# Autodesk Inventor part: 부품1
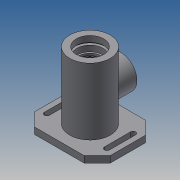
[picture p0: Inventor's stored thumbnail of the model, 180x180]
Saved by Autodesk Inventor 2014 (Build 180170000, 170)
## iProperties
Created: 2017-10
Part Number: 부품1
Material: 일반
Document SubType Name: Modeling
Designer: NET
Density: 1 g/cm^3
Appearance: 기본값
Author: NET
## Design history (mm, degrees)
sketch "스케치1"
  geometry: L1 (-58, 47)-(58, 47); L2 (58, 47)-(58, -47); L3 (58, -47)-(-58, -47); L4 (-58, -47)-(-58, 47); C1 r 31 at (0, 0); C2 r 35 at (0, 0); 3 further points
  constraints: 8 end point, 2 centre point, 2 coincident, 2 midpoint, 2 parallel, 1 horizontal, 1 horizontal alignment, 1 perpendicular, 1 vertical alignment
  dimensions: "d0" = 62 diameter of C1; "d1" = 116 distance of L1.start L1.end; "d2" = 94 distance of L1.end L2.end; "d3" = 70 diameter of C2
extrude "돌출1" new body sketch "스케치1" distance "d4" = 10; taper "d5" = 0 deg
extrude "돌출2" join sketch "스케치1" distance "d6" = 13; taper "d7" = 0 deg
extrude "돌출3" join sketch "스케치1" distance "d8" = 102; taper "d9" = 0 deg
chamfer "모따기1" distance "d10" = 20; stored, may be unused: second distance "d11" = 2, angle "d12" = 45 deg
node "작업 평면1"
sketch "스케치2"
  geometry: L1 (38, 0)-(-38, 0) reference; L2 (31, 102)-(-31, 102) reference; C1 r 25 at (0, 46); 2 further points
  constraints: 1 centre point, 1 midpoint, 1 vertical alignment
  dimensions: "d13" = 50 diameter of C1; "d14" = 56 distance from line of C1.centre L2
extrude "돌출4" join sketch "스케치2" stored distance "d15" = 32; taper "d16" = 0 deg
sketch "스케치3"
  geometry: L1 (-38, -47)-(38, -47) reference; L2 (-46, 20)-(-46, -20); L3 (-50, 20)-(-50, -20); L4 (-42, -20)-(-42, 20); L5 (46, 20)-(46, -20); L6 (42, 20)-(42, -20); L7 (50, -20)-(50, 20); C1 r 35 at (0, 0) reference; A1 r 4 centre (-46, 20) between (-42, 20) and (-50, 20); A2 r 4 centre (-46, -20) between (-50, -20) and (-42, -20); A3 r 4 centre (46, 20) between (50, 20) and (42, 20); A4 r 4 centre (46, -20) between (42, -20) and (50, -20); 2 further points
  constraints: 16 end point, 8 point on circle, 8 tangent, 4 centre point, 4 parallel, 2 horizontal alignment, 2 midpoint, 1 perpendicular
  dimensions: "d17" = 46 distance of point (-46, 0) C1.centre; "d18" = 92 distance of point (46, 0) point (-46, 0); "d19" = 40 distance of L5.end L5.start; "d20" = 4 radius of A3; "d21" = 4 radius of A1
extrude "돌출5" cut sketch "스케치3" distance "d22" = 32; taper "d23" = 0 deg
extrude "돌출6" join sketch "스케치1" distance "d24" = 13; taper "d25" = 0 deg
sketch "스케치4"
  geometry: L1 (31, 102)-(-31, 102) reference; L2 (31, 0)-(31, 102) reference; L3 (-31, 0)-(31, 0) reference; L4 (21, 93)-(24, 93); L5 (24, 93)-(24, 90); L6 (24, 90)-(20, 90); L7 (20, 90)-(20, 81); L8 (20, 81)-(17.5, 81); L9 (17.5, 81)-(17.5, 77.75); L10 (17.5, 77.75)-(18.5, 77.75); L11 (18.5, 77.75)-(18.5, 76); L12 (18.5, 76)-(17.5, 76); L13 (17.5, 76)-(17.5, 65); L14 (17.5, 65)-(23, 65); L15 (26, 62)-(26, 30); L16 (23, 27)-(17.5, 27); L17 (17.5, 27)-(17.5, 16.3); L18 (17.2, 16)-(16.5, 16); L19 (16.5, 16)-(16.5, 14); L20 (13.5, 11)-(10, 11); L21 (10, 11)-(10, 8.3); L22 (10, 8.3)-(12.2, 8.3); L23 (12.5, 8)-(12.5, 1.7); L24 (12.904, 1)-(14.022, 1); L25 (0, 102)-(0, 0); L26 (21, 93)-(21, 102); L27 (16.779, -0.818)-(22, -13); L28 (-35, -13)-(35, -13) reference; L29 (22, -13)-(0, -13); L30 (0, 0)-(0, -13); L31 (12.5, 1.7)-(12.904, 1); A1 r 3 centre (23, 30) between (23, 27) and (26, 30); A2 r 3 centre (23, 62) between (26, 62) and (23, 65); A3 r 3 centre (13.5, 14) between (13.5, 11) and (16.5, 14); A4 r 3 centre (14.022, -2) between (16.779, -0.818) and (14.022, 1); A5 r 0.3 centre (17.2, 16.3) between (17.2, 16) and (17.5, 16.3); A6 r 0.3 centre (12.2, 8) between (12.5, 8) and (12.2, 8.3); 7 further points
  constraints: 54 end point, 16 point on line, 14 perpendicular, 12 point on circle, 12 tangent, 10 parallel, 6 centre point, 4 equal radius, 2 collinear, 2 midpoint
  dimensions: "d26" = 42 diameter of L26 L25; "d27" = 40 diameter of L7 L25; "d28" = 48 diameter of L5 L25; "d29" = 35 diameter of L9 L25; "d30" = 37 diameter of L11 L25; "d31" = 52 diameter of L15 L25; "d33" = 33 diameter of L19 L25; "d34" = 20 diameter of L21 L25; "d35" = 25 diameter of L23 L25; "d36" = 32 diameter of point (16, 1) L25; "d38" = 12 distance from line of L26.end L6; "d39" = 3 distance of L4.end L5.end; "d40" = 21 distance from line of L1 L7.end; "d42" = 26 distance from line of L1 L11.end; "d43" = 1.75 distance of L10.end L11.end; "d44" = 38 distance of point (26, 65) point (26, 27); "d45" = 60 vertical distance of L12.end L18.end; "d46" = 14 distance from line of L24 L27.end; "d48" = 2.7 distance between parallel lines of L20 L22; "d49" = 7.3 distance between parallel lines of L22 L24; "d50" = 11 distance from line of L12.end L14; "d51" = 44 diameter of L27.end L25; "d53" = 3 radius of A1; "d54" = 0.3 radius of A5; "d55" = 0.7 distance of L23.end point (12.5, 1); "d56" = 30 deg angle of L23 L31
revolve "회전1" sketch "스케치4" stored, may be unused: angle "d52" = 90 deg
sketch "스케치5"
  geometry: C1 r 25 at (0, 0) reference; C2 r 16 at (0, 0); 1 further point
  constraints: 1 centre point, 1 coincident
  dimensions: "d57" = 32 diameter of C2
extrude "돌출7" cut sketch "스케치5" distance "d58" = 50; taper "d59" = 0 deg
node "솔리드1"
